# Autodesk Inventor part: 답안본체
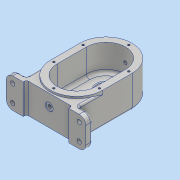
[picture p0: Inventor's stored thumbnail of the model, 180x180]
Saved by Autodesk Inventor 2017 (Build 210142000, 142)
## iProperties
Part Number: 답안본체
Material: 알루미늄 6061
Document SubType Name: Modeling
Designer: MRC
Density: 2.7 g/cm^3
Appearance: 알루미늄 - 평지
Mass: 756.755 g
Surface Area: 581.829 cm^2
Volume: 280.28 cm^3
Author: MRC
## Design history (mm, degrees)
sketch "스케치1"
  geometry: L1 (0, 0)-(0, -45); L2 (-40, 0)-(-40, -45); L3 (40, -45)-(40, 0); A1 r 40 centre (0, 0) between (40, 0) and (-40, 0); A2 r 40 centre (0, -45) between (-40, -45) and (40, -45); 2 further points
  constraints: 8 end point, 4 point on circle, 4 tangent, 2 centre point, 1 coincident, 1 midpoint, 1 parallel, 1 vertical
  dimensions: "d0" = 80 distance between parallel lines of L3 L2; "d1" = 45 distance of L1.end L1.start
extrude "돌출1" new body sketch "스케치1" stored distance "d2" = 49; taper "d3" = 0 deg
sketch "스케치2"
  geometry: L1 (-40, 0)-(-40, -45) reference; L2 (40, -45)-(40, 0) reference; L3 (-30, 0)-(-30, -45); L4 (30, -45)-(30, 0); A1 r 40 centre (0, -45) between (-40, -45) and (40, -45) reference; A2 r 40 centre (0, 0) between (40, 0) and (-40, 0) reference; A3 r 30 centre (0, -45) between (-30, -45) and (30, -45); A4 r 30 centre (0, 0) between (30, 0) and (-30, 0)
  constraints: 4 end point, 4 point on circle, 2 centre point, 3 other
  dimensions: "d4" = 10 radial gap between concentric circles of A2 A4
extrude "돌출2" cut sketch "스케치2" distance "d5" = 41; taper "d6" = 0 deg
sketch "스케치3"
  geometry: L1 (0, 0)-(0, -45); L2 (-26, 0)-(-26, -45); L3 (26, -45)-(26, 0); A1 r 40 centre (0, 0) between (40, 0) and (-40, 0) reference; A2 r 26 centre (0, 0) between (26, 0) and (-26, 0); A3 r 26 centre (0, -45) between (-26, -45) and (26, -45); 1 further point
  constraints: 8 end point, 4 point on circle, 4 tangent, 2 centre point, 1 midpoint, 1 parallel, 1 vertical
  dimensions: "d7" = 52 distance between parallel lines of L3 L2; "d8" = 45 distance of L1.end L1.start
extrude "돌출3" join sketch "스케치3" distance "d9" = 11; taper "d10" = 0 deg
sketch "스케치4"
  geometry: L1 (-26, 0)-(-26, -45) reference; L2 (26, -45)-(26, 0) reference; L3 (-26, 0)-(-26, -30); L4 (-26, -30)-(26, -30); L5 (26, 0)-(26, -45) reference; L6 (26, 0)-(26, -30); A1 r 26 centre (0, 0) between (26, 0) and (-26, 0) reference; A2 r 26 centre (0, 0) between (26, 0) and (-26, 0)
  constraints: 6 end point, 2 point on circle, 2 point on line, 1 centre point, 1 coincident, 1 collinear, 1 perpendicular
  dimensions: "d11" = 30 distance of L1.start L3.end
extrude "돌출4" cut sketch "스케치4" distance "d12" = 3; taper "d13" = 0 deg
sketch "스케치5"
  geometry: A1 r 26 centre (0, 0) between (26, 0) and (-26, 0) reference
hole "구멍1" sketch "스케치5" at (0, 0) diameter "d14" = 22; stored, may be unused: countersink angle "d18" = 90 deg, drill point angle "d20" = 118 deg; dims "d15" = 6, "d16" = 28, "d17" = 4, "d19" = 8
sketch "스케치6"
  geometry: A1 r 30 centre (0, -45) between (-30, -45) and (30, -45) reference
hole "구멍2" sketch "스케치6" diameter "d21" = 20; stored, may be unused: countersink angle "d25" = 90 deg, drill point angle "d27" = 0 deg; dims "d22" = 6, "d23" = 28, "d24" = 8, "d26" = 12
sketch "스케치7"
  geometry: C1 r 11 at (0, 0) reference
hole "구멍3" sketch "스케치7" at (0, 0) diameter "d28" = 28; stored, may be unused: countersink angle "d32" = 90 deg, drill point angle "d34" = 0 deg; dims "d29" = 6, "d30" = 28, "d31" = 8, "d33" = 8
node "작업 평면2"
sketch "스케치8"
  geometry: L1 (51, -24.5)-(-51, -24.5); L2 (-61, -14.5)-(-61, 11.5); L3 (-51, 21.5)-(51, 21.5); L4 (61, 11.5)-(61, -14.5); L5 (-40, -24.5)-(40, -24.5) reference; L6 (40, -24.5)-(40, 24.5) reference; L7 (40, -24.5)-(-40, -24.5); L8 (-40, -24.5)-(-40, 21.5); L9 (-40, 21.5)-(40, 21.5); L10 (40, 21.5)-(40, -24.5); A1 r 10 centre (51, -14.5) between (51, -24.5) and (61, -14.5); A2 r 10 centre (51, 11.5) between (61, 11.5) and (51, 21.5); A3 r 10 centre (-51, 11.5) between (-51, 21.5) and (-61, 11.5); A4 r 10 centre (-51, -14.5) between (-61, -14.5) and (-51, -24.5); 2 further points
  constraints: 16 end point, 8 point on circle, 8 tangent, 4 centre point, 4 parallel, 3 equal radius, 2 horizontal, 2 midpoint, 2 perpendicular, 1 point on line
  dimensions: "d37" = 46 distance between parallel lines of L3 L1; "d38" = 122 distance between parallel lines of L2 L4; "d39" = 10 radius of A1 (derived); "d42" = 80 distance between parallel lines of L8 L10
extrude "돌출5" join sketch "스케치8" distance "d40" = 10; taper "d41" = 0 deg
extrude "돌출6" join sketch "스케치8" stored distance "d43" = 10; taper "d44" = 0 deg
sketch "스케치9"
  geometry: A1 r 10 centre (-51, 14.5) between (-51, 24.5) and (-61, 14.5) reference; A2 r 10 centre (-51, -11.5) between (-61, -11.5) and (-51, -21.5) reference; A3 r 10 centre (51, 14.5) between (61, 14.5) and (51, 24.5) reference; A4 r 10 centre (51, -11.5) between (51, -21.5) and (61, -11.5) reference; 5 further points
  constraints: 4 coincident
hole "구멍4" sketch "스케치9" at (-51, 14.5), (-51, -11.5), (51, -11.5), (51, 14.5) diameter "d45" = 6.6; stored, may be unused: countersink angle "d49" = 90 deg, drill point angle "d51" = 0 deg; dims "d46" = 6, "d47" = 11, "d48" = 2, "d50" = 8
sketch "스케치10"
  geometry: A1 r 30 centre (0, 0) between (30, 0) and (-30, 0) reference; 1 further point
  constraints: 1 vertical alignment
  dimensions: "d52" = 35 distance of A1.centre point (0, 35)
hole "구멍5" sketch "스케치10" at (0, 35) diameter "d53" = 3.242; stored, may be unused: countersink angle "d57" = 90 deg, drill point angle "d59" = 118 deg; dims "d54" = 8, "d55" = 11, "d56" = 2, "d58" = 10
sketch "스케치11"
  geometry: A1 r 30 centre (0, -45) between (-30, -45) and (30, -45) reference; 1 further point
  constraints: 1 vertical alignment
  dimensions: "d63" = 35 distance of point (0, -80) A1.centre
hole "구멍6" sketch "스케치11" at (0, -80) diameter "d64" = 3.242; stored, may be unused: countersink angle "d68" = 90 deg, drill point angle "d70" = 118 deg; dims "d65" = 8, "d66" = 11, "d67" = 2, "d69" = 10
sketch "스케치12"
  geometry: L1 (51, 21.5)-(-51, 21.5) reference; L2 (-51, -24.5)-(51, -24.5) reference; L3 (-35, 21.5)-(35, 21.5); L4 (35, 21.5)-(35, -24.5); L5 (35, -24.5)-(-35, -24.5); L6 (-35, -24.5)-(-35, 21.5); 2 further points
  constraints: 8 end point, 2 midpoint, 2 parallel, 2 point on line, 1 horizontal, 1 perpendicular
  dimensions: "d74" = 70 distance between parallel lines of L4 L6
extrude "돌출7" cut sketch "스케치12" distance "d75" = 5; taper "d76" = 0 deg
sketch "스케치13"
  geometry: C1 r 14 at (0, 0) reference; 1 further point
  constraints: 1 vertical alignment
  dimensions: "d77" = 20 distance of C1.centre point (0, 20)
hole "구멍7" sketch "스케치13" at (0, 20) diameter "d78" = 3.242; stored, may be unused: countersink angle "d82" = 90 deg, drill point angle "d84" = 118 deg; dims "d79" = 8, "d80" = 11, "d81" = 2, "d83" = 10
fillet "모깎기1" dims "d88" = 5
sketch "스케치14"
  geometry: L1 (40, 24.5)-(-40, 24.5) reference; 2 further points
  constraints: 1 vertical alignment
  dimensions: "d132" = 21 distance from line of L1 point (0, 3.5)
hole "구멍8" sketch "스케치14" at (0, 3.5) diameter "d90" = 4.917; stored, may be unused: countersink angle "d94" = 90 deg, drill point angle "d96" = 0 deg; dims "d91" = 12, "d92" = 12, "d93" = 1, "d95" = 17.1
fillet "모깎기2" dims "d97" = 3
fillet "모깎기3" dims "d98" = 0.3
chamfer "모따기1" distance "d99" = 1; stored, may be unused: second distance "d100" = 2, angle "d101" = 45 deg
node "작업 평면3"
sketch "스케치15"
  geometry: L1 (40, 24.5)-(-40, 24.5) reference; C1 r 6 at (0, 3.5); 1 further point
  constraints: 1 centre point, 1 midpoint, 1 vertical alignment
  dimensions: "d120" = 12 diameter of C1; "d121" = 21 distance of C1.centre point (0, 24.5)
extrude "돌출8" join sketch "스케치15" stored distance "d104" = 5; taper "d105" = 0 deg
fillet "모깎기4" dims "d115" = 3
sketch "스케치16"
  geometry: L1 (-35, -92)-(-51, -92) reference; A1 r 37 centre (0, 0) between (37, 0) and (-37, 0) reference; 1 further point
  constraints: 1 vertical alignment, 1 other
  dimensions: "d116" = 12 distance from line of point (0, -80) L1
feature "엠보싱1" sketch "스케치16" dims "d117" = 0.5, "d118" = 0
fillet "모깎기5" dims "d122" = 3
hole "구멍10" diameter "d125" = 4.917; stored, may be unused: countersink angle "d129" = 90 deg, drill point angle "d131" = 0 deg; dims "d123" = 10, "d124" = 10, "d126" = 12, "d127" = 12, "d128" = 1, "d130" = 17.1
node "솔리드1"
pattern_circular "원형 패턴1" dims angle "d61" = 180 deg
pattern_circular "원형 패턴2" dims angle "d72" = 180 deg
pattern_circular "원형 패턴3" dims angle "d86" = 360 deg
other parameters: "d36" = -92, "d102" = -135
